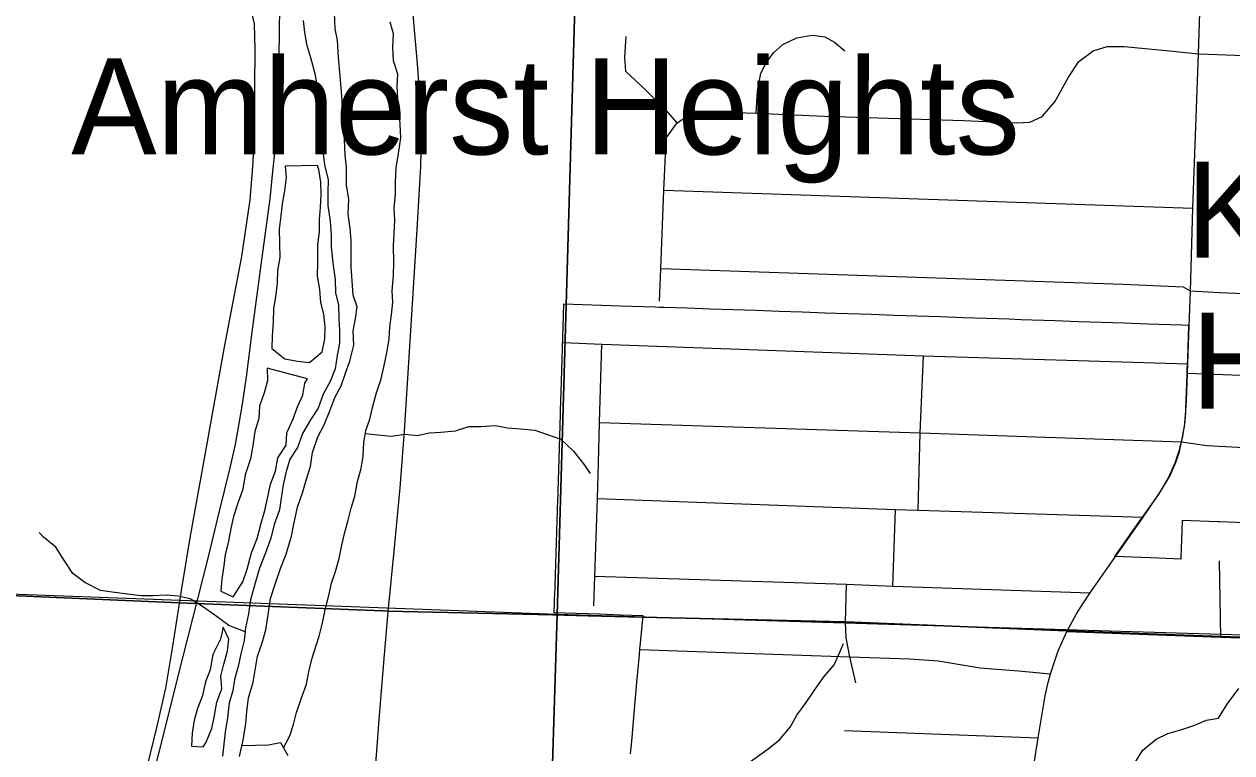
# Model space of a CAD drawing. Extents: x 0 to 34, y 0 to 22.
# Drawn here: x 3.672 to 4.666, y 14.832 to 15.431 of the extents above; entities that cross this region are included whole.
import ezdxf

# ---------------------------------------------------------------- set-up
doc = ezdxf.new("R2010")
doc.units = 0
for name, color, linetype in [('GM_X_City_Street', 7, 'Continuous'), ('GM_X_Corporation', 7, 'Continuous'), ('GM_X_Major_River', 7, 'Continuous'), ('GM_X_Minor_Lake', 7, 'Continuous'), ('GM_X_Minor_River', 7, 'Continuous'), ('GM_X_Rail_Line', 7, 'Continuous'), ('GM_X_State_Route', 7, 'Continuous'), ('GM_X_Township_Road', 7, 'Continuous'), ('GM_X_Unincorporated_Text', 7, 'Continuous')]:
    doc.layers.add(name, color=color, linetype=linetype)

msp = doc.modelspace()

# ---------------------------------------------------------------- linework, layer by layer
at = {"layer": 'GM_X_City_Street'}
for p, q in [((4.38681, 14.96905), (4.38898, 15.03208)), ((4.6567, 14.92694), (4.65551, 14.98973))]:
    msp.add_line(p, q, dxfattribs=at)
for points in [[(4.11588, 15.16936), (4.14749, 15.16809), (4.4121, 15.15852), (4.62951, 15.15176)], [(4.14455, 15.07023), (4.14532, 15.10343), (4.14749, 15.16809)], [(4.40758, 15.03136), (4.40939, 15.09512), (4.4121, 15.15852)], [(4.14532, 15.10343), (4.40939, 15.09512), (4.62443, 15.08755)], [(4.14081, 14.95279), (4.14171, 14.97718), (4.14388, 15.04093), (4.14455, 15.07023)], [(4.14388, 15.04093), (4.38898, 15.03208), (4.40758, 15.03136), (4.59289, 15.02559)], [(4.14171, 14.97718), (4.34879, 14.97057), (4.38681, 14.96905), (4.54927, 14.96347)], [(4.35637, 14.88945), (4.35155, 14.91093), (4.34834, 14.92651), (4.34798, 14.93896), (4.34879, 14.97057)], [(4.52993, 14.93168), (4.6567, 14.92694), (4.72966, 14.92455), (4.8672, 14.92178), (4.96288, 14.91707), (5.13372, 14.9121)], [(4.17838, 14.91685), (4.35155, 14.91093), (4.40081, 14.90915), (4.42423, 14.90755), (4.45882, 14.90169), (4.49022, 14.8993), (4.51657, 14.89682)], [(4.34708, 14.85011), (4.47026, 14.84559), (4.50632, 14.84428)]]:
    msp.add_lwpolyline(points, dxfattribs=at)
at = {"layer": 'GM_X_Corporation'}
for points in [[(3.11771, 16.24137), (3.10721, 15.7483), (3.08834, 15.37123), (3.08789, 15.36229), (3.08743, 15.35097), (3.07253, 14.98156), (3.42116, 14.97166), (3.42883, 14.97144), (3.43954, 14.97097), (3.7996, 14.95511), (3.96689, 14.94858), (3.97132, 14.94848), (4.1071, 14.94524), (4.13616, 14.94455), (4.18003, 14.94351), (4.34711, 14.93953), (4.34778, 14.93951), (4.52973, 14.93223), (4.65649, 14.92749), (4.72946, 14.92509), (4.867, 14.92233), (4.96267, 14.91762), (5.13352, 14.91265), (5.21811, 14.9126)], [(4.6833, 15.02088), (4.65556, 15.02184), (4.65416, 15.02189), (4.62486, 15.0229), (4.62431, 15.007), (4.62382, 14.99287), (4.62376, 14.99119), (4.60565, 14.9919), (4.58391, 14.99276), (4.57634, 14.99306), (4.56957, 14.99332), (4.58056, 15.00892), (4.59155, 15.02451), (4.59234, 15.02563), (4.60343, 15.04137), (4.60389, 15.04203), (4.60435, 15.04269), (4.60454, 15.04296), (4.60486, 15.04342), (4.60536, 15.04416), (4.60541, 15.04424), (4.60585, 15.04491), (4.60616, 15.04537), (4.60637, 15.04569), (4.60668, 15.04618), (4.60683, 15.04641), (4.6072, 15.047), (4.60731, 15.04716), (4.60822, 15.04863), (4.60865, 15.04933), (4.60906, 15.05001), (4.60923, 15.0503), (4.60952, 15.05078), (4.60972, 15.05113), (4.60997, 15.05155), (4.61021, 15.05197), (4.61041, 15.05233), (4.61069, 15.05281), (4.61085, 15.0531), (4.61088, 15.05314), (4.61116, 15.05366), (4.61129, 15.05388), (4.61163, 15.0545), (4.61172, 15.05467), (4.61253, 15.05618), (4.61255, 15.05621), (4.61292, 15.05692), (4.61328, 15.05762), (4.61335, 15.05775), (4.61344, 15.05793), (4.61366, 15.05837), (4.61388, 15.0588), (4.61404, 15.05913), (4.61413, 15.0593), (4.61431, 15.05966), (4.61442, 15.05989), (4.61473, 15.06053), (4.61479, 15.06064), (4.61489, 15.06087), (4.61515, 15.06141), (4.61564, 15.06245), (4.61636, 15.06403), (4.61706, 15.06563), (4.61774, 15.06723), (4.6184, 15.06884), (4.61904, 15.07046), (4.61966, 15.07209), (4.62026, 15.07373), (4.62083, 15.07537), (4.62139, 15.07702), (4.62192, 15.07868), (4.62243, 15.08035), (4.62292, 15.08202), (4.62339, 15.0837), (4.62383, 15.08538), (4.62426, 15.08707), (4.62453, 15.0882), (4.62466, 15.08877), (4.62504, 15.09047), (4.6254, 15.09217), (4.62573, 15.09388), (4.62605, 15.0956), (4.62634, 15.09731), (4.62661, 15.09904), (4.62685, 15.10076), (4.62708, 15.10249), (4.62728, 15.10422), (4.62746, 15.10595), (4.62761, 15.10769), (4.62775, 15.10942), (4.62786, 15.11116), (4.62795, 15.1129), (4.62802, 15.11464), (4.62851, 15.12904), (4.62874, 15.13574), (4.62904, 15.14436), (4.62912, 15.14683), (4.62929, 15.15157), (4.62945, 15.1563), (4.63038, 15.18338), (4.6247, 15.18357), (4.5963, 15.18454), (4.57726, 15.18519), (4.55843, 15.18584), (4.53939, 15.18649), (4.52045, 15.18714), (4.50152, 15.18779), (4.49216, 15.18811), (4.48259, 15.18844), (4.46365, 15.18908), (4.44483, 15.18973), (4.4259, 15.19038), (4.40696, 15.19102), (4.38791, 15.19168), (4.36898, 15.19232), (4.35016, 15.19297), (4.33122, 15.19362), (4.31218, 15.19427), (4.29336, 15.19491), (4.27442, 15.19556), (4.25549, 15.19621), (4.23655, 15.19686), (4.21756, 15.19751), (4.19869, 15.19815), (4.1949, 15.19828), (4.19111, 15.19841), (4.17218, 15.19906), (4.16271, 15.19939), (4.11594, 15.20099), (4.11536, 15.18241), (4.1151, 15.17391), (4.1148, 15.16444), (4.11424, 15.14664), (4.11367, 15.12846), (4.11321, 15.11375), (4.1131, 15.11028), (4.11253, 15.0921), (4.11196, 15.07374), (4.1114, 15.0558), (4.11084, 15.03787), (4.11072, 15.03431), (4.11027, 15.01993), (4.11017, 15.01656), (4.10971, 15.00199), (4.10962, 14.99907), (4.10914, 14.98382), (4.10908, 14.98169), (4.10857, 14.96564), (4.10854, 14.96445), (4.108, 14.94733), (4.1453, 14.94607), (4.16314, 14.94547), (4.18098, 14.94487), (4.17895, 14.92203), (4.1785, 14.91731), (4.17808, 14.91258), (4.17602, 14.88977), (4.17461, 14.87408), (4.17167, 14.84136), (4.17073, 14.83094)], [(5.21811, 14.9126), (5.13352, 14.91265), (4.96267, 14.91762), (4.867, 14.92233), (4.72946, 14.92509), (4.65649, 14.92749), (4.52973, 14.93223), (4.34778, 14.93951), (4.34711, 14.93953), (4.18003, 14.94351), (4.13616, 14.94455), (4.1071, 14.94524), (3.97132, 14.94848), (3.96689, 14.94858), (3.7996, 14.95511), (3.43954, 14.97097)]]:
    msp.add_lwpolyline(points, dxfattribs=at)
for points in [[(3.11259, 15.99841), (4.14019, 15.96398), (4.11057, 14.94555), (3.0765, 14.98408)], [(4.14019, 15.96398), (5.1712, 15.93073), (5.12979, 14.91483), (4.11057, 14.94555)], [(3.04628, 14.12039), (4.08493, 14.12039), (4.11057, 14.94555), (3.0765, 14.98408)], [(4.08493, 14.12039), (5.10726, 14.12039), (5.12979, 14.91483), (4.11057, 14.94555)]]:
    msp.add_lwpolyline(points, close=True, dxfattribs=at)
at = {"layer": 'GM_X_Major_River'}
for points in [[(3.84929, 14.82887), (3.85226, 14.84216), (3.85447, 14.85584), (3.85519, 14.86571), (3.85665, 14.8771), (3.86038, 14.89002), (3.86408, 14.91129), (3.86782, 14.92232), (3.8708, 14.93296), (3.87301, 14.94739), (3.87485, 14.95878), (3.87897, 14.97133), (3.88308, 14.98349), (3.88757, 14.99527), (3.89206, 15.0101), (3.89391, 15.01997), (3.89688, 15.03403), (3.90137, 15.04657), (3.90398, 15.05607), (3.90772, 15.06748), (3.90918, 15.07887), (3.91367, 15.09179), (3.91893, 15.10168), (3.92343, 15.11309), (3.92755, 15.12411), (3.93282, 15.13362), (3.93656, 15.14426), (3.93993, 15.15414), (3.94328, 15.16706), (3.94285, 15.17883), (3.9447, 15.1887), (3.94617, 15.19858), (3.94271, 15.20844), (3.9419, 15.2202), (3.94109, 15.23121), (3.94099, 15.25322), (3.94018, 15.26309), (3.93861, 15.27523), (3.93931, 15.287), (3.93736, 15.29914), (3.9373, 15.31319), (3.93611, 15.32343), (3.93567, 15.33634), (3.93449, 15.3462), (3.93406, 15.35721), (3.93363, 15.36859), (3.93282, 15.37884), (3.93202, 15.38833), (3.93081, 15.40389), (3.92999, 15.41793), (3.92805, 15.42741), (3.9272, 15.44715)], [(3.90148, 15.43415), (3.90266, 15.42428), (3.90422, 15.4148), (3.90768, 15.4038), (3.91116, 15.39053), (3.91272, 15.38105), (3.91542, 15.36967), (3.91585, 15.35904), (3.91628, 15.34803), (3.91937, 15.33666), (3.9179, 15.32678), (3.91909, 15.3154), (3.92218, 15.30326), (3.92185, 15.29263), (3.92189, 15.282), (3.92385, 15.2691), (3.92466, 15.25772), (3.92471, 15.24785), (3.92629, 15.23267), (3.92786, 15.22129), (3.92829, 15.2099), (3.93061, 15.20042), (3.93104, 15.18903), (3.93147, 15.17916), (3.93152, 15.16892), (3.92967, 15.15866), (3.92782, 15.14765), (3.9237, 15.13738), (3.91806, 15.12673), (3.91394, 15.11533), (3.90754, 15.10581), (3.90115, 15.0944), (3.89703, 15.083), (3.89063, 15.07348), (3.88727, 15.06208), (3.88504, 15.05221), (3.88357, 15.04119), (3.8821, 15.0317), (3.87761, 15.01953), (3.875, 15.00851), (3.87051, 14.99635), (3.86564, 14.98381), (3.86228, 14.9724), (3.85818, 14.95759), (3.85671, 14.94619), (3.85411, 14.93479), (3.85302, 14.92416), (3.85042, 14.91314), (3.84819, 14.90288), (3.84521, 14.89224), (3.84373, 14.88275), (3.84074, 14.87287), (3.83928, 14.86071)], [(3.83928, 14.86071), (3.83744, 14.84894), (3.83526, 14.82919)]]:
    msp.add_lwpolyline(points, dxfattribs=at)
at = {"layer": 'GM_X_Minor_Lake'}
for points in [[(3.88686, 15.31452), (3.88766, 15.30503), (3.8862, 15.29402), (3.88435, 15.28338), (3.88326, 15.27351), (3.88179, 15.26249), (3.88223, 15.25073), (3.88228, 15.23934), (3.88043, 15.2287), (3.8801, 15.21845), (3.87901, 15.20896), (3.87717, 15.19718), (3.87684, 15.18617), (3.87613, 15.17479), (3.8758, 15.16453), (3.88646, 15.15584), (3.89708, 15.15398), (3.90694, 15.15288), (3.91714, 15.16165), (3.91937, 15.17229), (3.9197, 15.18216), (3.91851, 15.19278), (3.9162, 15.20227), (3.91539, 15.21289), (3.91344, 15.22389), (3.91377, 15.23528), (3.9137, 15.24971), (3.91517, 15.26034), (3.91512, 15.27059), (3.91584, 15.28046), (3.91654, 15.29147), (3.91612, 15.30134), (3.91455, 15.31158), (3.9134, 15.315)], [(3.9134, 15.315), (3.88686, 15.31452)], [(3.87208, 15.1482), (3.87213, 15.13795), (3.86952, 15.12807), (3.86578, 15.11705), (3.86507, 15.10679), (3.86171, 15.09615), (3.86024, 15.08476), (3.8584, 15.07374), (3.85391, 15.06044), (3.85207, 15.04867), (3.84757, 15.0365), (3.84421, 15.02624), (3.84198, 15.01636), (3.83976, 15.00459), (3.83753, 14.99509), (3.83643, 14.98559), (3.83459, 14.97496), (3.83387, 14.96471), (3.84413, 14.96019), (3.85204, 14.97237), (3.8554, 14.98301), (3.85913, 14.99631), (3.86363, 15.00809), (3.86698, 15.02063), (3.86997, 15.03127), (3.8722, 15.04115), (3.8748, 15.05293), (3.87892, 15.06357), (3.88076, 15.07459), (3.88754, 15.08486), (3.88825, 15.09511), (3.89351, 15.10652), (3.89688, 15.1164), (3.90138, 15.12591), (3.90285, 15.13579), (3.90511, 15.13959)], [(3.90511, 15.13959), (3.87208, 15.1482)], [(3.8193, 14.83673), (3.82156, 14.84015), (3.82643, 14.85194), (3.82866, 14.86257), (3.8305, 14.87359), (3.83462, 14.88461), (3.83382, 14.89486), (3.83643, 14.90474), (3.83941, 14.91538), (3.8405, 14.92525), (3.83591, 14.93511), (3.83368, 14.92523), (3.82729, 14.91268), (3.82507, 14.90014), (3.82133, 14.89026), (3.81872, 14.87886), (3.8146, 14.86822), (3.81199, 14.85872), (3.81014, 14.84808), (3.80982, 14.83745)], [(3.80982, 14.83745), (3.8193, 14.83673)]]:
    msp.add_lwpolyline(points, dxfattribs=at)
at = {"layer": 'GM_X_Minor_River'}
for points in [[(3.88547, 14.83606), (3.89054, 14.84572), (3.89353, 14.85522), (3.89614, 14.8651), (3.89988, 14.87613), (3.90437, 14.88829), (3.90622, 14.89855), (3.90883, 14.90881), (3.91481, 14.92781), (3.91741, 14.93883), (3.91964, 14.94946), (3.92262, 14.96124), (3.92484, 14.9715), (3.92821, 14.981), (3.9312, 14.99164), (3.93342, 15.00266), (3.93565, 15.01216), (3.93826, 15.02204), (3.94124, 15.03306), (3.94423, 15.04294), (3.94645, 15.05509), (3.94943, 15.06573), (3.9509, 15.07599), (3.95161, 15.087), (3.95308, 15.09687), (3.95645, 15.10638), (3.95868, 15.11587), (3.96166, 15.12727), (3.96578, 15.13944), (3.96838, 15.15045), (3.9706, 15.16223), (3.97245, 15.17248), (3.97279, 15.18236), (3.97426, 15.19223), (3.97535, 15.20248), (3.97492, 15.21197), (3.976, 15.2245), (3.97633, 15.23551), (3.97589, 15.2488), (3.9766, 15.25905), (3.97693, 15.26968), (3.9765, 15.27993), (3.97759, 15.2917), (3.97754, 15.30119), (3.97825, 15.31296), (3.98009, 15.32473), (3.98193, 15.33765), (3.9815, 15.34903), (3.98068, 15.36042), (3.9795, 15.3699), (3.97907, 15.38053), (3.97941, 15.39002), (3.97595, 15.40102), (3.97551, 15.4124), (3.97584, 15.42341), (3.97314, 15.43289)], [(3.95274, 15.09455), (3.97396, 15.09239), (3.98532, 15.09395), (3.99557, 15.09286), (4.00542, 15.09517), (4.01489, 15.09558), (4.02702, 15.09677), (4.038, 15.10023), (4.04786, 15.10026), (4.05999, 15.10106), (4.06986, 15.0992), (4.08048, 15.09848), (4.09224, 15.09739), (4.1135, 15.08988), (4.12417, 15.08005), (4.13218, 15.06945), (4.1379, 15.0615)], [(3.85375, 14.93127), (3.84045, 14.93664), (3.82904, 14.94495), (3.81877, 14.95212), (3.8085, 14.95854), (3.79863, 14.96078), (3.78877, 14.9615), (3.77815, 14.96108), (3.76792, 14.96105), (3.74439, 14.96399), (3.73491, 14.96548), (3.72198, 14.97188), (3.71209, 14.97944), (3.70522, 14.98966), (3.69796, 15.00102), (3.68807, 15.00934), (3.68426, 15.01312)], [(4.26792, 14.82321), (4.28303, 14.83427), (4.29361, 14.84266), (4.30229, 14.85295), (4.30793, 14.86284), (4.31546, 14.87311), (4.32224, 14.88339), (4.33015, 14.89443), (4.33845, 14.90433), (4.34333, 14.91459), (4.34633, 14.92182)], [(4.58641, 14.82439), (4.59244, 14.8339), (4.60339, 14.84306), (4.61323, 14.84765), (4.62459, 14.85111), (4.63443, 14.85418), (4.64503, 14.85877), (4.65488, 14.86033), (4.66203, 14.87174), (4.67145, 14.88468)], [(3.85132, 14.83794), (3.86252, 14.83803), (3.87313, 14.83845), (3.88298, 14.84038), (3.8891, 14.82977)]]:
    msp.add_lwpolyline(points, dxfattribs=at)
at = {"layer": 'GM_X_Rail_Line'}
msp.add_lwpolyline([(3.75746, 14.73175), (3.78562, 14.84186), (3.79878, 14.8949), (3.82331, 14.99201), (3.83288, 15.03069), (3.84165, 15.06618), (3.84584, 15.08533), (3.84883, 15.10267), (3.85162, 15.11863), (3.85505, 15.14104), (3.85978, 15.17783), (3.86759, 15.23745), (3.8744, 15.28744), (3.87639, 15.3072), (3.87822, 15.3253), (3.87954, 15.34424), (3.88021, 15.36068), (3.8812, 15.37978), (3.8817, 15.39921), (3.88204, 15.4198), (3.88311, 15.54282)], dxfattribs=at)
at = {"layer": 'GM_X_State_Route'}
for points in [[(3.9622, 14.8333), (3.96389, 14.8558), (3.96769, 14.9028), (3.97152, 14.94793), (3.97432, 14.97553), (3.97662, 14.99774), (3.98136, 15.04968), (3.98509, 15.09647), (3.99294, 15.22284), (3.99572, 15.26706), (3.99856, 15.31412), (3.99897, 15.34026), (3.99856, 15.35997), (3.99592, 15.39539), (3.99189, 15.44257)], [(3.94935, 14.6623), (3.96098, 14.81693), (3.9622, 14.8333)]]:
    msp.add_lwpolyline(points, dxfattribs=at)
at = {"layer": 'GM_X_Township_Road'}
msp.add_line((4.19852, 15.29465), (4.63377, 15.27985), dxfattribs=at)
for points in [[(4.6309, 15.18985), (4.63185, 15.21155), (4.63377, 15.27985), (4.63827, 15.40694), (4.64027, 15.46626), (4.64194, 15.52918), (4.64431, 15.58623), (4.6465, 15.64581), (4.65524, 15.88547), (4.65705, 15.94382), (4.65974, 16.01803), (4.6616, 16.07173)], [(3.80158, 14.96537), (3.80868, 15.00857), (3.82032, 15.07399), (3.83658, 15.16419), (3.85107, 15.24017), (3.85811, 15.28676), (3.86055, 15.31737), (3.86163, 15.34988), (3.86217, 15.41029), (3.86163, 15.43141), (3.85757, 15.44875), (3.84999, 15.46311), (3.83888, 15.4753), (3.82588, 15.48369), (3.81823, 15.48681), (3.8099, 15.48911), (3.79175, 15.49101), (3.71021, 15.49697), (3.69071, 15.49913), (3.68218, 15.50137), (3.67493, 15.50428), (3.66802, 15.508)], [(4.20012, 15.33328), (4.20022, 15.33581), (4.20058, 15.33809), (4.2094, 15.35016), (4.20139, 15.35916), (4.18421, 15.37634), (4.17454, 15.38551), (4.16703, 15.39235), (4.1662, 15.40369), (4.16737, 15.42104)], [(4.27444, 15.358), (4.27544, 15.37618), (4.27828, 15.39085), (4.28278, 15.40002), (4.28878, 15.40803), (4.29629, 15.41437), (4.30796, 15.41987), (4.32064, 15.42221), (4.33098, 15.42087), (4.33882, 15.41637), (4.34732, 15.40936)], [(4.2094, 15.35016), (4.2174, 15.35533), (4.22824, 15.3585), (4.24008, 15.35916), (4.27444, 15.358), (4.33048, 15.35549), (4.44506, 15.35199), (4.48858, 15.34999), (4.49943, 15.35066), (4.50977, 15.35516), (4.52027, 15.36734), (4.53128, 15.38768), (4.5398, 15.40061), (4.55163, 15.40936), (4.5633, 15.41287), (4.57715, 15.41287), (4.61484, 15.4092), (4.63827, 15.40694), (4.63926, 15.4069)], [(4.63926, 15.4069), (4.85767, 15.39852), (4.86184, 15.39552)], [(4.19473, 15.2033), (4.19584, 15.2299), (4.19852, 15.29465), (4.19996, 15.32949), (4.20012, 15.33328)], [(4.63677, 15.21126), (4.63185, 15.21155), (4.6261, 15.21497), (4.57623, 15.21714), (4.19584, 15.2299)], [(5.14737, 15.19304), (5.01069, 15.19696), (4.85125, 15.2023), (4.65545, 15.21013), (4.63677, 15.21126)], [(4.55039, 14.96506), (4.56387, 14.98415), (4.59289, 15.02559), (4.60656, 15.04611), (4.61482, 15.05928), (4.62007, 15.07146), (4.62276, 15.07957), (4.62443, 15.08755), (4.62676, 15.10023), (4.62768, 15.10932), (4.62835, 15.12174), (4.62918, 15.14401), (4.62951, 15.15176), (4.6306, 15.18295), (4.6309, 15.18985)], [(4.62918, 15.14401), (4.84875, 15.13605), (5.00802, 15.13005), (5.14503, 15.12555)], [(4.62443, 15.08755), (4.64534, 15.08452), (4.72188, 15.08063), (4.73056, 15.07734), (4.73653, 15.07196), (4.74969, 15.00319), (4.74999, 14.99272), (4.747, 14.97896), (4.74252, 14.9694), (4.73414, 14.95535)], [(3.74301, 14.70465), (3.75261, 14.73973), (3.76745, 14.79648), (3.78145, 14.85363), (3.78863, 14.88505), (3.79446, 14.91959), (3.79981, 14.95456), (3.80158, 14.96537)], [(4.53459, 14.94018), (4.53785, 14.94612), (4.5436, 14.95529), (4.54927, 14.96347), (4.55039, 14.96506)], [(4.45964, 14.55394), (4.46777, 14.60497), (4.48353, 14.70267), (4.48511, 14.71321), (4.49779, 14.79077), (4.50632, 14.84428), (4.51213, 14.87883), (4.51453, 14.88971), (4.51657, 14.89682), (4.52284, 14.9156), (4.52993, 14.93168), (4.53459, 14.94018)]]:
    msp.add_lwpolyline(points, dxfattribs=at)

# ---------------------------------------------------------------- texts
at = {"layer": 'GM_X_Unincorporated_Text'}
for s, height, p in [('Amherst Heights', 0.0789773, (3.71073, 15.3241)), ('Kendall', 0.078977, (4.62823, 15.2391)), ('Heights', 0.078977, (4.6324, 15.11494))]:
    msp.add_text(s, height=height, rotation=0.00001, dxfattribs=at).set_placement(p)

doc.saveas('drawing.dxf')
